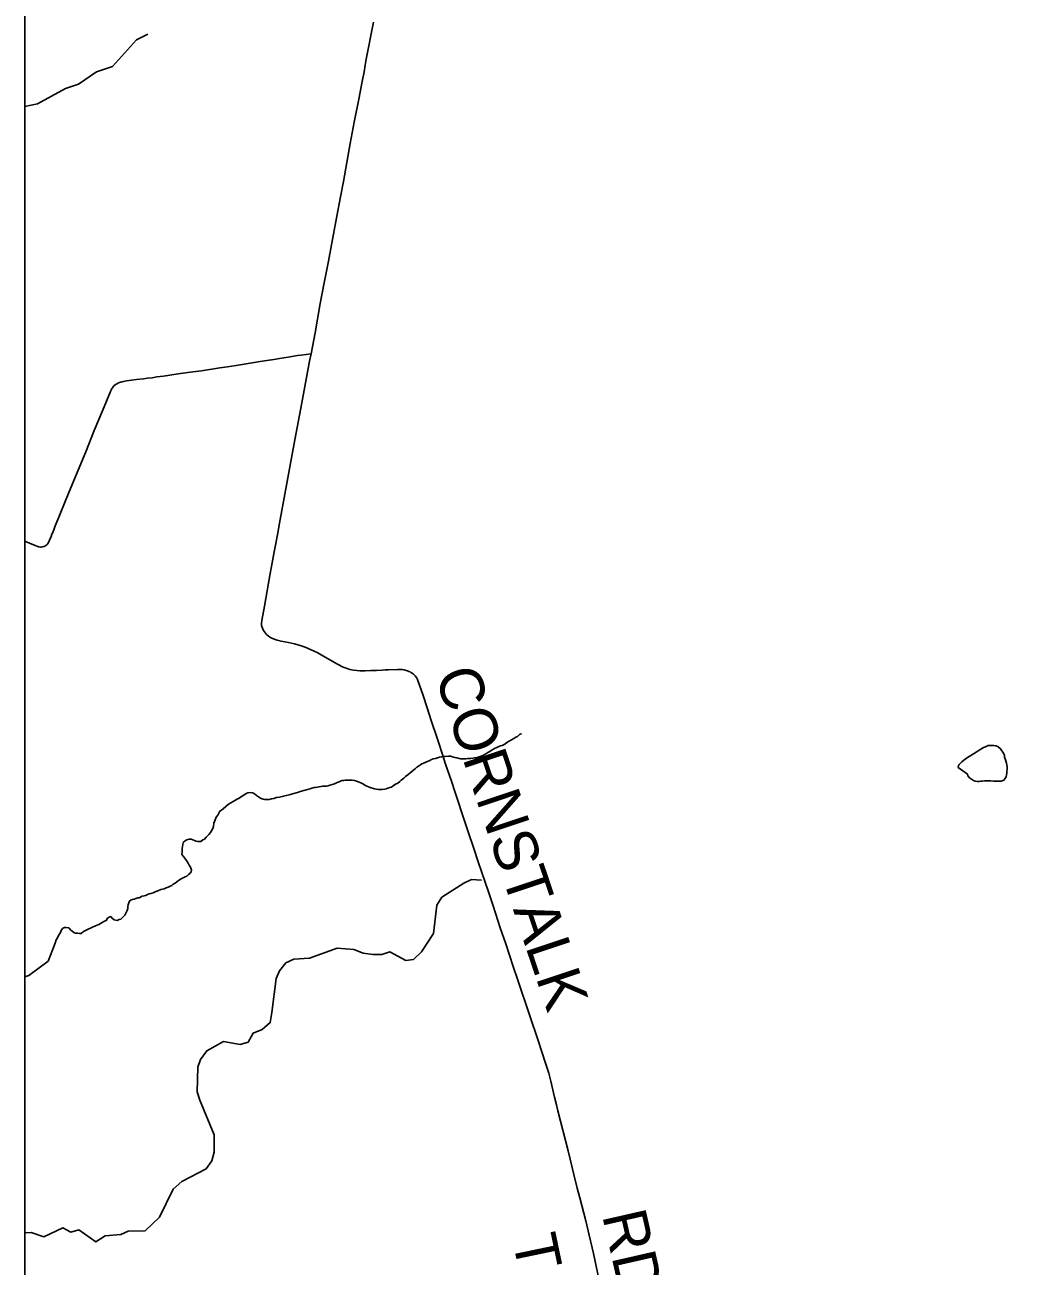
# Model space of a CAD drawing. Extents: x 0 to 34, y 0 to 22.
# Drawn here: x 9.538 to 10.834, y 15.473 to 17.083 of the extents above; entities that cross this region are included whole.
import ezdxf

# ---------------------------------------------------------------- set-up
doc = ezdxf.new("R2010")
doc.units = 0
for name, color, linetype in [('GM_X_Corporation', 7, 'Continuous'), ('GM_X_Minor_Lake', 7, 'Continuous'), ('GM_X_Minor_River', 7, 'Continuous'), ('GM_X_Township_Road', 7, 'Continuous'), ('GM_X_Township_Road_Text', 7, 'Continuous')]:
    doc.layers.add(name, color=color, linetype=linetype)

msp = doc.modelspace()

# ---------------------------------------------------------------- linework, layer by layer
at = {"layer": 'GM_X_Corporation'}
msp.add_lwpolyline([(16.3375, 14.3932), (16.3375, 21.1059), (9.5375, 21.1059), (9.5375, 15.0426), (9.5452, 15.0418), (9.7185, 15.0258), (10.2502, 14.9799), (10.3112, 14.9746), (10.787, 14.9212), (11.3129, 14.8754), (11.3292, 14.8742), (12.1361, 14.7923), (13.6754, 14.6095), (14.714, 14.5341), (15.778, 14.4476), (16.0263, 14.4243)], close=True, dxfattribs=at)
msp.add_lwpolyline([(9.5375, 21.1059), (9.5375, 15.0426), (9.5452, 15.0418), (9.7185, 15.0258), (10.2502, 14.9799), (10.3112, 14.9746), (10.787, 14.9212), (11.3129, 14.8754), (11.3292, 14.8742), (12.1361, 14.7923), (13.6754, 14.6095)], dxfattribs=at)
at = {"layer": 'GM_X_Minor_Lake'}
msp.add_lwpolyline([(10.7479, 16.1198), (10.7483, 16.1209), (10.7494, 16.1236), (10.7529, 16.127), (10.7575, 16.1307), (10.7624, 16.1341), (10.7681, 16.1375), (10.7716, 16.1394), (10.7739, 16.1413), (10.7811, 16.1454), (10.7834, 16.1465), (10.7868, 16.1484), (10.7914, 16.1484), (10.7945, 16.148), (10.7971, 16.1479), (10.7994, 16.1468), (10.8032, 16.1437), (10.8047, 16.1414), (10.8062, 16.1395), (10.8073, 16.1372), (10.8081, 16.1353), (10.8084, 16.133), (10.8092, 16.1308), (10.8099, 16.1281), (10.811, 16.1254), (10.8118, 16.1205), (10.8117, 16.117), (10.8113, 16.1144), (10.8113, 16.1121), (10.8109, 16.1102), (10.8102, 16.1076), (10.8086, 16.1049), (10.8075, 16.103), (10.804, 16.1019), (10.7987, 16.1019), (10.7941, 16.102), (10.79, 16.1024), (10.7854, 16.1024), (10.7824, 16.1024), (10.7793, 16.1021), (10.7774, 16.1017), (10.7751, 16.1013), (10.7728, 16.1014), (10.7702, 16.1018), (10.7679, 16.1029), (10.7653, 16.1045), (10.7634, 16.106), (10.7607, 16.1087), (10.76, 16.111), (10.7479, 16.1198)], dxfattribs=at)
at = {"layer": 'GM_X_Minor_River'}
for points in [[(9.5901, 17.0007), (9.6072, 17.0063), (9.6303, 17.0224), (9.6513, 17.0295), (9.6824, 17.0638), (9.697, 17.0714)], [(9.5375, 16.9773), (9.554, 16.981), (9.5901, 17.0007)], [(10.0211, 16.0995), (10.0238, 16.1014), (10.0257, 16.1033), (10.0291, 16.1059), (10.0311, 16.1078), (10.0341, 16.1101), (10.0372, 16.1127), (10.0391, 16.1142), (10.0421, 16.1165), (10.0441, 16.1184), (10.046, 16.1199), (10.0483, 16.1214), (10.0506, 16.1233), (10.0525, 16.1244), (10.0559, 16.1259), (10.0586, 16.127), (10.062, 16.1285), (10.065, 16.13), (10.0673, 16.1307), (10.07, 16.1315), (10.0753, 16.133), (10.078, 16.1333), (10.0803, 16.1341), (10.0829, 16.1341), (10.0871, 16.1344), (10.0898, 16.1344), (10.0921, 16.1336), (10.0951, 16.1328), (10.0978, 16.132), (10.1008, 16.1313), (10.1027, 16.1309), (10.1054, 16.1309), (10.1095, 16.1308), (10.1122, 16.1312), (10.1156, 16.1312), (10.1187, 16.1319), (10.121, 16.1323), (10.1229, 16.1323), (10.127, 16.1334), (10.1293, 16.1345), (10.1324, 16.1356), (10.1354, 16.1375), (10.1381, 16.139), (10.1408, 16.1405), (10.1438, 16.1424), (10.1469, 16.1442), (10.1496, 16.1457), (10.1522, 16.1469), (10.1545, 16.1476), (10.1568, 16.1484), (10.1599, 16.1499), (10.1625, 16.1521), (10.1717, 16.1574), (10.1744, 16.1589), (10.1767, 16.16), (10.1793, 16.1623), (10.1812, 16.1634), (10.1816, 16.1634)], [(9.7594, 16.0242), (9.7617, 16.0238), (9.7636, 16.0238), (9.7659, 16.0238), (9.7682, 16.0257), (9.7701, 16.0264), (9.7727, 16.0291), (9.7762, 16.0325), (9.7785, 16.0351), (9.7796, 16.0374), (9.7812, 16.0404), (9.782, 16.0431), (9.7827, 16.0473), (9.7843, 16.0518), (9.7858, 16.0552), (9.7878, 16.0579), (9.7893, 16.0605), (9.7905, 16.0628), (9.7927, 16.0643), (9.7947, 16.0658), (9.8015, 16.0722), (9.8046, 16.0737), (9.8077, 16.0756), (9.8099, 16.0767), (9.8122, 16.0782), (9.8145, 16.0793), (9.8168, 16.0808), (9.8187, 16.082), (9.8214, 16.0839), (9.8244, 16.0857), (9.8267, 16.0869), (9.8302, 16.0872), (9.8328, 16.0868), (9.8351, 16.0857), (9.8381, 16.0834), (9.8419, 16.0807), (9.8442, 16.0795), (9.8465, 16.0787), (9.8484, 16.0783), (9.8514, 16.0779), (9.8544, 16.0783), (9.8575, 16.079), (9.8605, 16.0794), (9.864, 16.0805), (9.8678, 16.0812), (9.8731, 16.0823), (9.8765, 16.0831), (9.8803, 16.0842), (9.8834, 16.0849), (9.8864, 16.0857), (9.8895, 16.0868), (9.8925, 16.0875), (9.8948, 16.0883), (9.9013, 16.0901), (9.9043, 16.0912), (9.9078, 16.092), (9.9097, 16.0927), (9.9127, 16.0935), (9.9146, 16.0938), (9.9169, 16.0942), (9.9192, 16.0946), (9.9215, 16.0949), (9.9234, 16.0953), (9.9272, 16.0953), (9.9291, 16.0956), (9.931, 16.096), (9.9333, 16.0967), (9.9363, 16.0975), (9.939, 16.0986), (9.9424, 16.1001), (9.9451, 16.1012), (9.947, 16.102), (9.9493, 16.1027), (9.9512, 16.1027), (9.9531, 16.1031), (9.955, 16.1034), (9.9576, 16.1034), (9.9599, 16.103), (9.9622, 16.103), (9.9652, 16.1026), (9.9679, 16.1018), (9.9713, 16.1006), (9.9732, 16.0999), (9.9766, 16.0979), (9.9785, 16.0968), (9.9812, 16.0953), (9.9831, 16.0945), (9.9853, 16.0937), (9.991, 16.0918), (9.9937, 16.0914), (9.996, 16.091), (9.9979, 16.091), (10.0009, 16.0913), (10.0043, 16.0917), (10.0062, 16.092), (10.0085, 16.0928), (10.0108, 16.0935), (10.0131, 16.0943), (10.0154, 16.0958), (10.0184, 16.098), (10.0211, 16.0995)], [(9.5679, 15.8681), (9.5768, 15.8917), (9.5783, 15.8959), (9.5795, 15.8978), (9.5802, 15.8997), (9.5822, 15.9031), (9.5837, 15.9057), (9.5845, 15.908), (9.5864, 15.9107), (9.5891, 15.9122), (9.591, 15.9122), (9.5944, 15.9114), (9.597, 15.9087), (9.5989, 15.9072), (9.6012, 15.9056), (9.6031, 15.9048), (9.6057, 15.9048), (9.6084, 15.9044), (9.6107, 15.9044), (9.6137, 15.9067), (9.6172, 15.9086), (9.6198, 15.9097), (9.6225, 15.9112), (9.6252, 15.9123), (9.629, 15.9142), (9.6336, 15.916), (9.6378, 15.9187), (9.6408, 15.9202), (9.6431, 15.9209), (9.6447, 15.9239), (9.6469, 15.9254), (9.6489, 15.9262), (9.6507, 15.9239), (9.6534, 15.922), (9.6572, 15.9212), (9.6599, 15.9223), (9.6621, 15.9227), (9.6644, 15.9253), (9.6671, 15.928), (9.6687, 15.9306), (9.6702, 15.934), (9.671, 15.9367), (9.671, 15.9393), (9.6714, 15.9412), (9.6722, 15.9439), (9.6733, 15.9462), (9.6752, 15.9477), (9.6771, 15.9484), (9.6794, 15.9488), (9.6813, 15.9495), (9.684, 15.9503), (9.6859, 15.9506), (9.6897, 15.9525), (9.6924, 15.9532), (9.6943, 15.9536), (9.6966, 15.9547), (9.6989, 15.9555), (9.7011, 15.9562), (9.7038, 15.957), (9.7065, 15.9581), (9.7099, 15.9596), (9.7137, 15.9615), (9.7183, 15.9622), (9.7206, 15.9633), (9.7233, 15.9644), (9.7259, 15.9656), (9.7282, 15.9667), (9.7301, 15.9682), (9.7324, 15.9697), (9.737, 15.9731), (9.7401, 15.975), (9.742, 15.9761), (9.7454, 15.9776), (9.7477, 15.9787), (9.7496, 15.9806), (9.7515, 15.9821), (9.7534, 15.9844), (9.7538, 15.9866), (9.7523, 15.9901), (9.7508, 15.9931), (9.7493, 15.9954), (9.7471, 15.9989), (9.7444, 16.0023), (9.7433, 16.0042), (9.741, 16.0069), (9.7414, 16.0092), (9.7414, 16.0118), (9.7415, 16.0145), (9.7419, 16.0171), (9.7423, 16.0198), (9.743, 16.0221), (9.7457, 16.0247), (9.7476, 16.0258), (9.7507, 16.0266), (9.7533, 16.0266), (9.7552, 16.0258), (9.7575, 16.025), (9.7594, 16.0242)], [(9.5621, 15.5107), (9.5868, 15.5221), (9.597, 15.5165), (9.6077, 15.5197), (9.6297, 15.504), (9.6416, 15.512), (9.6618, 15.5135), (9.6717, 15.5178), (9.6934, 15.5184), (9.712, 15.5359), (9.7298, 15.5723), (9.741, 15.5823), (9.7725, 15.599), (9.7799, 15.6091), (9.7832, 15.6204), (9.7829, 15.6429), (9.7646, 15.6881), (9.761, 15.6989), (9.762, 15.7307), (9.7653, 15.7409), (9.7735, 15.7521), (9.795, 15.7642), (9.8169, 15.7602), (9.8272, 15.763), (9.8336, 15.7747), (9.8454, 15.7797), (9.8559, 15.7886), (9.8577, 15.8018), (9.8635, 15.8458), (9.8676, 15.8559), (9.8761, 15.866), (9.8865, 15.8707), (9.9066, 15.8721), (9.9425, 15.885), (9.9641, 15.8833), (9.9762, 15.8785), (9.9887, 15.877), (10.0004, 15.8768), (10.0108, 15.8803), (10.0318, 15.8692), (10.0417, 15.8705), (10.0521, 15.8805), (10.0674, 15.9041), (10.072, 15.9408), (10.0783, 15.9513), (10.1071, 15.9696), (10.1167, 15.9743), (10.13, 15.9733)], [(9.5375, 15.8479), (9.5426, 15.8497), (9.5679, 15.8681)], [(9.5375, 15.5158), (9.5456, 15.5163), (9.5621, 15.5107)]]:
    msp.add_lwpolyline(points, dxfattribs=at)
at = {"layer": 'GM_X_Township_Road'}
for points in [[(9.9087, 16.6565), (9.9139, 16.6837), (9.9207, 16.7216), (9.9258, 16.7485), (9.9312, 16.7765), (9.9351, 16.7979), (9.9421, 16.8352), (9.9469, 16.8602), (9.9507, 16.8803), (9.9596, 16.9292), (9.9648, 16.9573), (9.9705, 16.9871), (9.975, 17.0097), (9.9775, 17.0225), (9.979, 17.031), (9.9804, 17.0389), (9.9897, 17.087)], [(9.5621, 16.4064), (9.5635, 16.407), (9.5648, 16.4077), (9.566, 16.4085), (9.5669, 16.4096), (9.5675, 16.4105), (9.5681, 16.4115), (9.5694, 16.4148), (9.5715, 16.4194), (9.5726, 16.4224), (9.5736, 16.4247), (9.5754, 16.4293), (9.577, 16.4334), (9.5803, 16.4414), (9.5824, 16.4466), (9.59, 16.465), (9.5967, 16.4817), (9.6164, 16.5294), (9.6275, 16.5571), (9.6381, 16.5823), (9.6486, 16.6075), (9.6495, 16.6094), (9.6504, 16.6113), (9.651, 16.6124), (9.6519, 16.6136), (9.6531, 16.6151), (9.6546, 16.6162), (9.6559, 16.6171), (9.6576, 16.6181), (9.6589, 16.6187), (9.6604, 16.6193), (9.6619, 16.6198), (9.6634, 16.6202), (9.6693, 16.6213), (9.6822, 16.623), (9.6915, 16.6241), (9.6964, 16.6247), (9.7026, 16.6255), (9.7087, 16.6264), (9.7173, 16.6276), (9.7364, 16.6303), (9.7555, 16.633), (9.7666, 16.6346), (9.7905, 16.6382), (9.8004, 16.6397), (9.8114, 16.6415), (9.8298, 16.6445), (9.8402, 16.6462), (9.8482, 16.6474), (9.8544, 16.6484), (9.8605, 16.6493), (9.8679, 16.6504), (9.8789, 16.6522), (9.8912, 16.6541), (9.896, 16.6547), (9.9087, 16.6565)], [(10.2818, 15.4561), (10.2749, 15.489), (10.2696, 15.5126), (10.2651, 15.5314), (10.2574, 15.5614), (10.254, 15.5737), (10.2496, 15.5916), (10.2422, 15.6221), (10.2289, 15.674), (10.227, 15.6817), (10.2247, 15.6917), (10.2198, 15.7127), (10.217, 15.7229), (10.213, 15.736), (10.2033, 15.7655), (10.1927, 15.7973), (10.1767, 15.845), (10.171, 15.8615), (10.1612, 15.8909), (10.1541, 15.9114), (10.1451, 15.94), (10.1388, 15.9581), (10.1302, 15.9834), (10.1255, 15.9974), (10.1204, 16.0134), (10.1118, 16.0387), (10.1053, 16.0581), (10.099, 16.0769), (10.0951, 16.0887), (10.0908, 16.1017), (10.0832, 16.124), (10.0786, 16.138), (10.074, 16.1527), (10.0697, 16.1656), (10.0673, 16.1729), (10.0647, 16.1805), (10.062, 16.1887), (10.0594, 16.197), (10.054, 16.2129), (10.0469, 16.2338), (10.0454, 16.2366), (10.0438, 16.2386), (10.0419, 16.2404), (10.0399, 16.242), (10.0383, 16.243), (10.0372, 16.2436), (10.0355, 16.2444), (10.0338, 16.2451), (10.032, 16.2457), (10.0296, 16.2463), (10.0271, 16.2467), (10.0246, 16.2468), (10.0208, 16.247), (10.009, 16.2465), (10.0047, 16.2463), (10.001, 16.2461), (9.9936, 16.2457), (9.9862, 16.2453), (9.979, 16.245), (9.9759, 16.245), (9.9722, 16.2451), (9.968, 16.2453), (9.964, 16.2458), (9.9589, 16.2469), (9.9543, 16.2484), (9.9503, 16.25), (9.9431, 16.2536), (9.9271, 16.2626), (9.9166, 16.2687), (9.9088, 16.2725), (9.901, 16.2758), (9.8948, 16.278), (9.8871, 16.2802), (9.8794, 16.2817), (9.8699, 16.2835), (9.865, 16.2847), (9.8587, 16.2869), (9.8552, 16.2889), (9.8511, 16.2924), (9.8484, 16.2956), (9.8471, 16.2975), (9.8456, 16.3003), (9.8446, 16.3037), (9.8445, 16.3071), (9.8448, 16.3102), (9.8482, 16.3288), (9.8558, 16.3714), (9.8582, 16.3853), (9.861, 16.3994), (9.862, 16.4061), (9.8651, 16.4214), (9.8679, 16.4367), (9.8875, 16.5447), (9.8967, 16.5928), (9.9069, 16.6471), (9.9087, 16.6565)], [(9.5375, 16.4135), (9.5434, 16.4109), (9.5509, 16.4078), (9.5529, 16.407), (9.5542, 16.4065), (9.5552, 16.4062), (9.5563, 16.4059), (9.5576, 16.4057), (9.5586, 16.4057), (9.5599, 16.4058), (9.5621, 16.4064)]]:
    msp.add_lwpolyline(points, dxfattribs=at)

# ---------------------------------------------------------------- texts
at = {"layer": 'GM_X_Township_Road_Text'}
for s, height, rotation, p in [('CORNSTALK', 0.05682, 288.4704, (10.0688, 16.24)), ('RD', 0.05682, 282.8473, (10.2861, 15.5387)), ('T', 0.0568, 281.7957, (10.1696, 15.5079))]:
    msp.add_text(s, height=height, rotation=rotation, dxfattribs=at).set_placement(p)

doc.saveas('drawing.dxf')
